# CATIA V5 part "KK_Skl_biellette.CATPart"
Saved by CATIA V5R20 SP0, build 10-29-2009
Part number: Skl_biellette
Publications: "Droite.6", "Axe_pivot_biellette_maneton", "Axe_pivot_scie_biellette", "Point.3", "Plan.Ref5", "Point.4", "Plan_Ref1"
Bounding box of the stored display mesh (mm): x -7.5 to 32.5, y 85 to 135, z 0 to 0
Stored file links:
  G:\Khaled_CFAO_2011\ST2M\ST2M_GR2\aandujar\Khaled\CAD_thinkMOTION\KK_Skl_biellette.CATPart
  G:\Khaled_CFAO_2011\ST2M\ST2M_GR2\aandujar\Khaled\CAD_thinkMOTION\KK_Skl_scie_mecanique.CATProduct
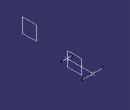
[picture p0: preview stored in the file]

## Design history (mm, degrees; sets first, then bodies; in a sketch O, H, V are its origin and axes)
WSupportSet1: ActiveGrid {3dwsupport RefPoint {point stored without definition}, 3DWOS ({wsupport Support xy-plane, RefPoint {3dwsupport}, GridIn {cartgrid Value 100, Stepbid1 0, Value 100, Stepbid2 0, Direction (1, 0, 0)}, GeometricData ({line type PtDir, Direction (1, 0, 0), Support xy-plane}; {line type PtDir, Direction (0, 1, 0), Support yz-plane})}; {wsupport Support yz-plane, RefPoint {3dwsupport}, GridIn {cartgrid Value 100, Stepbid1 0, Value 100, Stepbid2 0, Direction (0, 1, 0)}, GeometricData ({line type PtDir, Direction (0, 1, 0), Support yz-plane}; {line type PtDir, Direction (0, 0, 1), Support zx-plane})}; {wsupport Support zx-plane, RefPoint {3dwsupport}, GridIn {cartgrid Value 100, Stepbid1 0, Value 100, Stepbid2 0, Direction (0, 0, 1)}, GeometricData ({line type PtDir, Direction (0, 0, 1), Support zx-plane}; {line type PtDir, Direction (1, 0, 0), Support xy-plane})}), GeometricData ({line type PtDir, RefPoint {point stored without definition}, Direction (1, 0, 0), Support xy-plane}; {line type PtDir, RefPoint {point stored without definition}, Direction (0, 1, 0), Support yz-plane}; {line type PtDir, RefPoint {point stored without definition}, Direction (0, 0, 1), Support zx-plane})}
Set1
  Line1: type PtPt, FirstPoint Point2, SecondPoint Point1
  Line2 "Axe_pivot_biellette_maneton": type Normal, RefPoint Point1, RefSkin Plane2, Start -10, End 10
  Line3 "Axe_pivot_scie_biellette": type Normal, RefPoint Point2, RefSkin Plane2, Start -20, End 20
Set2
  Point1: linked copy from another document
  Plane1 "Plan.Ref5": linked copy from another document
  Point2: linked copy from another document
  Plane2 "Plan_Ref1": linked copy from another document
Body1 (main body)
